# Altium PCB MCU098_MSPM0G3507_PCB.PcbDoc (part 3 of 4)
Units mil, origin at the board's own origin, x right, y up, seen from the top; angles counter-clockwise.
Board outline 2310.03 x 4205.03 mil, 4 copper layers (Top Layer, VCC Layer, GND Layer, Bottom Layer), stack 62.4 mil thick; 260 components, 182 nets, 835 pads, 237 vias.
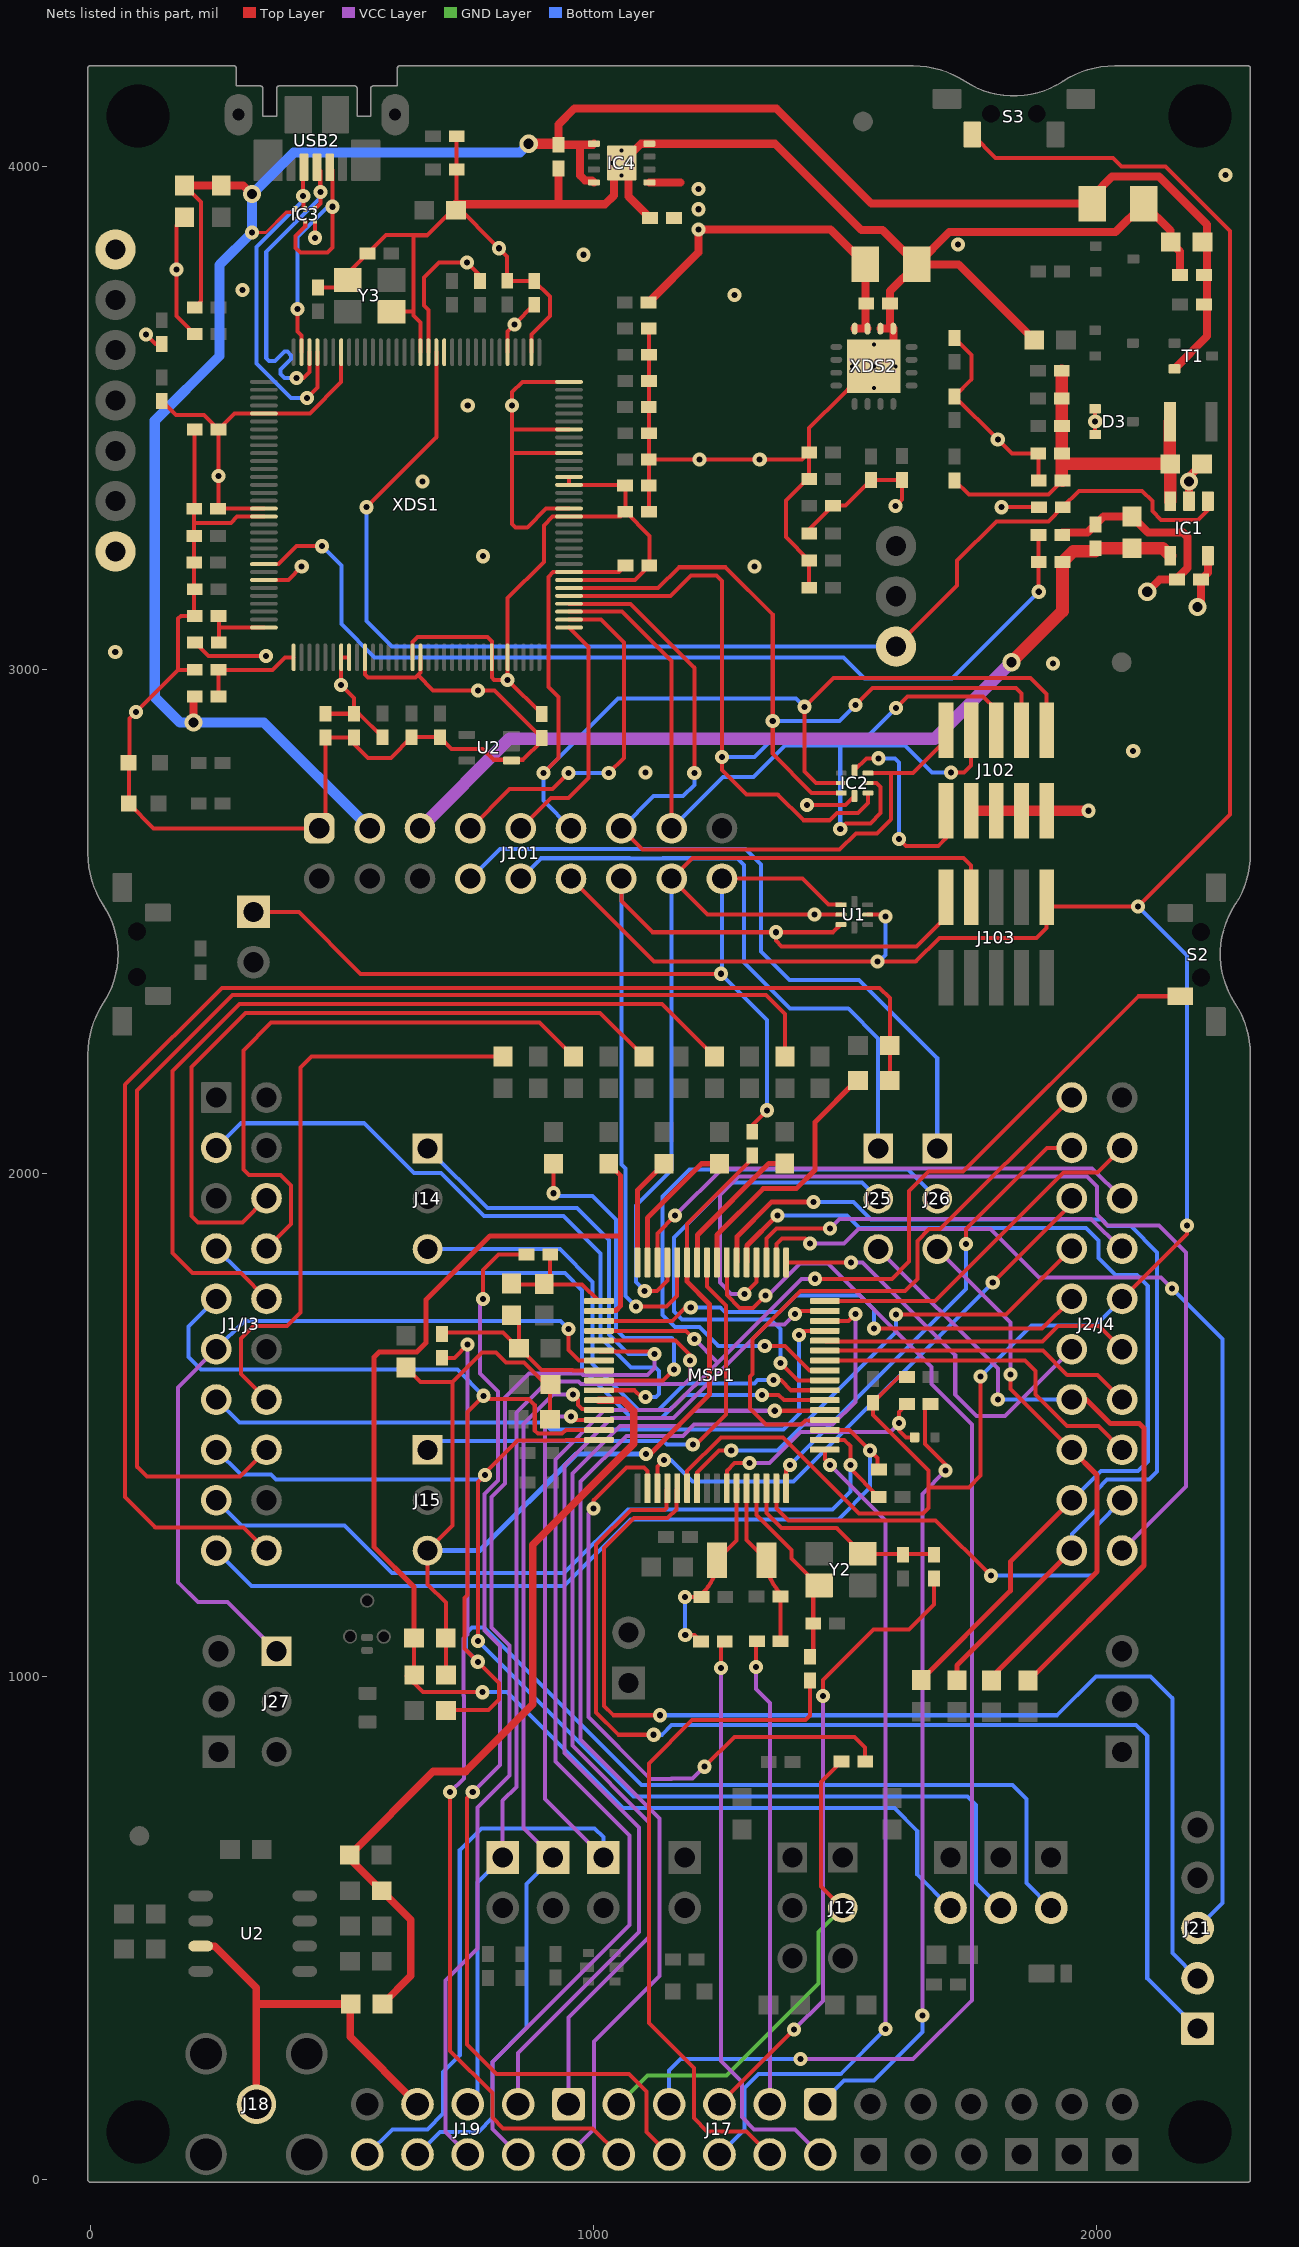
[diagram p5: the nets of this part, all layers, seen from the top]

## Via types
v1: diameter 28, hole 12, Top Layer to Bottom Layer, 211 vias
v2: diameter 36, hole 20, Top Layer to Bottom Layer, 17 vias
v3: diameter 19.68, hole 7.87, Top Layer to Bottom Layer, 9 vias

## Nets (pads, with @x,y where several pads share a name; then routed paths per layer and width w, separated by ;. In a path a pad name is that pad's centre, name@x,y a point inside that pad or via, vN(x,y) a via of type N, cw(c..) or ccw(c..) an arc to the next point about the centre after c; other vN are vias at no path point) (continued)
PA1: MSP1.34 R19.1 | length 1278.6
  Top Layer w8: v1(999.96,1333.33) 999.96,1349.91 1065.04,1414.99 1078.33,1414.99 1078.57,1415.23 1100.26,1415.23 1107.05,1408.44 MSP1.34@1107.05,1373.59 ; v1(1220,820.5) 1279.5,880 1518,880 1539.62,858.38 R19.1@1539.62,830.5
  VCC Layer w8: v1(999.96,1333.33) 990,1323.36 990,919 1112.5,796.5 1154.63,796.5 1154.75,796.62 1196.12,796.62 v1(1220,820.5)
PA1-: J12.2 J17.9 R19.2 | length 991.2
  Top Layer w8: R19.2@1492.38,830.5 1452,790.12 1452,582.88 J12.2@1494.88,540
  GND Layer w8: J17.9@1050,150 1107,207 1264,207 1447,390 1447,492.12 J12.2@1494.88,540
PA2-: J17.1 R9.1 | length 1579
  Top Layer w8: R9.1@1669.62,1541 1658.83,1530.2 1658.83,1461.99 1699.39,1421.43 v1(1699.39,1409)
  VCC Layer w8: v1(1653.02,326.02) 1653.02,1362.63 v1(1699.39,1409)
  Bottom Layer w8: J17.1@1470,170 J17.1@1450,150 1450.8,150 1497.8,197 1557,197 1653.02,293.02 v1(1653.02,326.02)
PA2_ROSC: MSP1.42 R8.1 R9.2 | length 512.1
  Top Layer w8: MSP1.42@1264.53,1373.59 1264.53,1408.53 1280,1424 v1(1310,1424) ; R9.2@1622.38,1541 1607,1525.62 v1(1607,1503) 1607,1489 1621,1475 R8.1@1637.82,1475 R8.1@1638.38,1475
  VCC Layer w8: v1(1310,1424) 1349,1424 1411,1486 1590,1486 v1(1607,1503)
PA3-: J17.2 R10.1 | length 1151.8
  Top Layer w8: v1(1253.03,1017) 1253.03,1060.64 1252.65,1061.02 R10.1@1260.62,1069
  VCC Layer w8: v1(1253.03,1017) 1253.03,236.45 1252.65,236.06 1294.35,194.35 1294.35,124.65 1319,100 1400,100 J17.2@1450,50
PA3_LFXIN: C9.2 MSP1.43 R10.2 Y1.2 | length 390.3
  Top Layer w8: v1(1181.65,1158) C9.2@1214.38,1158 ; v1(1182,1082) 1200.38,1082 R10.2@1213.38,1069 ; C9.2@1208.26,1158.65 ccw(c1155.34,1231) Y1.2@1244.98,1231 1284.21,1270.23 MSP1.43@1284.21,1373.59 MSP1.43@1285.4,1372.4
  Bottom Layer w8: v1(1181.65,1158) 1182,1157.65 v1(1182,1082)
PA4-: J17.3 R11.1 | length 935.8
  Top Layer w8: v1(1322.9,1019) 1322.9,1068.27 R11.1@1324.38,1069.75
  VCC Layer w8: v1(1322.9,1019) 1322.9,974.48 1350,947.38 J17.3@1350,150
  Bottom Layer w8: J17.3@1347,153 J17.3@1350,150
PA4_LFXOUT: C11.2 MSP1.44 R11.2 Y1.1 | length 330.5
  Top Layer w8: MSP1.44@1303.9,1373.59 1303.9,1270.51 Y1.1@1343.4,1231 ccw(c1434.2,1231) C11.2@1378.31,1159.45 ; C11.2@1370.96,1158.65 1370.96,1070.41 R11.2@1371.62,1069.75
PA5-: J17.4 R15.1 | length 1351.7
  Top Layer w8: J17.4@1350,50 1304,96 1225.58,96 1199,122.58 1199,222 1109.62,311.38 1109.62,827.19 1195.43,913 1420.58,913 1430,922.42 R15.1@1430,991.63
PA5_HFXIN: C10.2 MSP1.45 R15.2 Y2.3 | length 394.5
  Top Layer w8: MSP1.45@1323.58,1373.59 1323.58,1320.29 1393,1250.88 1393,1234.33 1446.82,1180.5 Y2.3@1448.05,1180.5 1436.38,1168.83 C10.2@1436.38,1105 1436.38,1045.25 R15.2@1430,1038.87
PA6-: J17.5 R17.1 | length 1262.3
  Top Layer w8: J17.5@1250,150 v1(1398,298) ; v1(1456,961) 1456,993 1556.25,1093.25 1626.75,1093.25 1676.38,1142.88 R17.1@1676.38,1194.38
  VCC Layer w8: v1(1398,298) 1455.35,355.35 1455.35,960.35 v1(1456,961)
PA6_HFXOUT: C12.2 MSP1.46 R17.2 Y2.1 | length 416.4
  Top Layer w8: MSP1.46@1343.27,1373.59 1343.27,1324.73 1372.88,1295.12 1483.04,1295.12 Y2.1@1534.66,1243.5 1674.5,1243.5 R17.2@1676.38,1241.62
PA7_CLK-OUT: J17.6 MSP1.49 | length 1682.5
  Top Layer w8: MSP1.49@1459.41,1450.36 1459.41,1430.59 v1(1470,1420)
  VCC Layer w8: v1(1470,1420) 1580,1310 v1(1580,299)
  Bottom Layer w8: J17.6@1250,50 1300,100 1300,182 1328,210 1491,210 v1(1580,299)
PA8_UART1-TX: J1/J3.4 MSP1.54 | length 1463.6
  Top Layer w8: v1(1334.84,1559.36) 1367.56,1559.36 1378.12,1548.79 MSP1.54@1459.41,1548.79
  Bottom Layer w8: J1/J3.4@250,1850 299,1801 943.19,1801 977.23,1766.97 977.23,1611.32 1075.32,1513.23 1135.02,1513.23 1181.14,1559.36 v1(1334.84,1559.36)
PA9_UART1-RX: J14.3 MSP1.55 | length 1053.4
  Top Layer w8: v1(1357.4,1588.56) 1372.09,1588.56 1392.17,1568.47 MSP1.55@1459.41,1568.47 MSP1.55@1457.5,1566.57
  Bottom Layer w8: J14.3@670,1849 933,1849 998,1784 998,1620.43 1089.33,1529.1 1128.44,1529.1 1181.34,1582 1319.47,1582 1326.03,1588.56 v1(1357.4,1588.56)
PA10_UART0-TX: J25.2 MSP1.56 | length 1006
  Top Layer w8: v1(1371.1,1623) 1405.94,1588.16 MSP1.56@1459.41,1588.16
  Bottom Layer w8: v1(1371.1,1623) 1371.1,1689.75 1351.84,1709 1175.85,1709 1160,1724.85 1160,1871.97 1269.03,1981 1533.39,1981 J25.2@1565.39,1949
PA10_UART0-TX_BP: J2/J4.34 J25.3 R62.2 | length 1299.4
  Top Layer w10: R62.2@1870.5,997.5 2093.39,1220.39 2093.39,1493.28 2084.66,1502 2026.83,1502 1978.83,1550 J2/J4.34@1950,1550
  VCC Layer w8: J25.3@1565.39,1849 1803,1611.39 v1(1803,1550)
  Bottom Layer w8: v1(1803,1550) J2/J4.34@1950,1550
PA10_UART0-TX_XDS: J25.1 J101.10 | length 1208.3
  Bottom Layer w8: J101.10@855.36,2585 J101.10@855,2585 895.51,2625.51 1071.78,2625.51 1072.21,2625.08 1137.79,2625.08 1138.22,2625.51 1285.49,2625.51 1299,2612 1299,2418 1390,2327 1505.91,2327 1565.39,2267.52 J25.1@1565.39,2049
PA11_UART0-RX: J26.2 MSP1.57 | length 1195.9
  Top Layer w8: v1(1340,1656.33) 1380.58,1656.33 1429.06,1607.84 MSP1.57@1459.41,1607.84 MSP1.57@1460.44,1608.87
  Bottom Layer w8: v1(1340,1656.33) 1247.61,1656.33 1209.94,1694 1161.41,1694 1137.28,1718.13 1137.28,1953.27 1190.69,2006.68 1625.04,2006.68 J26.2@1682.72,1949
PA11_UART0-RX_BP: J2/J4.33 J26.3 R63.2 | length 1075.7
  Top Layer w8: v1(1828.25,1599.89) 1828.25,1571.09 1949.34,1450 J2/J4.33@1950,1450
  Top Layer w10: R63.2@1790.84,991.75 1790.84,998.84 2000,1208 2000,1400 J2/J4.33@1950,1450
  VCC Layer w8: J26.3@1682.72,1849 1828.25,1703.47 v1(1828.25,1599.89)
PA11_UART0-RX_XDS: J26.1 J101.8 | length 1404.2
  Bottom Layer w8: J101.8@755,2585 813.84,2643.84 1301.67,2643.84 1332.87,2612.64 1332.87,2440.6 1389.62,2383.85 1527.08,2383.85 1682.72,2228.2 J26.1@1682.72,2049
PA12_CAN-TX: J2/J4.32 MSP1.5 R64.2 | length 1946.6
  Top Layer w10: MSP1.5@1303.9,1822.41 1304.8,1823.32 1304.8,1856.16 1364.64,1916 v1(1365,1916) ; R64.2@1650.84,992.75 1828,1169.91 1828,1228 J2/J4.32@1950,1350
  Bottom Layer w8: v1(1365,1916) 1503.25,1916 1528.4,1890.86 1978.74,1890.86 2003.52,1866.07 2003.52,1831.21 2036.9,1797.83 2079.21,1797.83 2101,1776.03 2101,1427 2081.63,1407.63 2007.63,1407.63 J2/J4.32@1950,1350
PA13_CAN-RX: J2/J4.31 MSP1.6 R65.2 | length 2020.6
  Top Layer w10: MSP1.6@1284.21,1822.41 1285.12,1823.31 1285.12,1874.12 1353.87,1942.87 1436.38,1942.87 v1(1437.13,1942.13) ; R65.2@1721.84,992.25 1721.84,1021.84 J2/J4.31@1950,1250
  Bottom Layer w8: v1(1437.13,1942.13) 1516.36,1942.13 1551.04,1907.44 2009.76,1907.44 2022.36,1894.84 2067.38,1894.84 2119.69,1842.53 2119.69,1407 2103.69,1391 2020.36,1391 2000,1370.64 2000,1332.89 1950,1282.89 J2/J4.31@1950,1250
PA14_TIMH0-C0: J17.7 MSP1.7 | length 2626.2
  Top Layer w8: MSP1.7@1264.53,1822.41 1264.53,1757.47 1290,1732 1316.83,1732 v1(1341.69,1756.86) v1@1341.69,1751.92
  VCC Layer w8: v1(1341.69,1756.86) 1346.64,1756.86 1409.78,1820 1465.67,1820 1671,1614.67 1671,1581 1751.48,1500.52 1751.48,356.48 1635,240 v1(1410.76,240)
  Bottom Layer w8: J17.7@1150,150 1150,217 1173,240 v1(1410.76,240)
PA15-_DAC-OUT: C45.1 J1/J3.30 R55.2 | length 2915.9
  Top Layer w8: J1/J3.30@350,1250 304,1296 129,1296 69,1356 69,2175.5 261.31,2367.81 1568.19,2367.81 1588.53,2347.47 C45.1@1588.53,2253.53 1588.53,2184.09 R55.2@1588.19,2183.75
PA15_DAC-OUT: MSP1.8 R55.1 | length 517.5
  Top Layer w10: MSP1.8@1244.84,1822.41 1244.84,1876.84 1337,1969 1402.68,1969 1439.73,2006.05 1439.73,2101 1522.48,2183.75 R55.1@1525.19,2183.75
PA16_OPA1-OUT_ADC1.1: J15.1 MSP1.9 | length 947.7
  Top Layer w8: v1(1197,1460.41) 1203.17,1460.41 1262.72,1519.96 1262.72,1736.83 1225.16,1774.39 MSP1.9@1225.16,1822.41
  Bottom Layer w8: J15.1@670,1450 690,1470 692.13,1467.87 1138.22,1467.87 1145.68,1460.41 v1(1197,1460.41)
PA17-_ADC1.2: J1/J3.28 R81.1 | length 2500.1
  Top Layer w8: J1/J3.28@350,1450 297.21,1397.21 112.29,1397.21 93,1416.5 93,2164 282.82,2353.81 1342.19,2353.81 1380,2316 R81.1@1380,2231.5
PA17_OPA1-IN-_ADC1.2: MSP1.10 R82.2 | length 287.4
  Top Layer w10: MSP1.10@1205.47,1822.41 1206.38,1823.32 1206.38,1877.02 1348.62,2019.25 R82.2@1379.84,2019.25
PA18-: J8.1 J101.18 R23.1 U1.5 | length 1791.5
  Top Layer w8: J8.1@324.12,2518.97 414.28,2518.97 537.25,2396 v1(1253.01,2396) ; J101.18@1255,2585 1414.56,2585 1466.39,2533.17 U1.5@1491.35,2533.17 ; R23.1@1315.24,2082.16 1315.24,2095.31 v1(1344.68,2124.75)
  Bottom Layer w8: J101.18@1255,2585 1255,2397.99 v1(1253.01,2396) 1344.68,2304.33 v1(1344.68,2124.75)
PA18_OPA1-IN+_ADC1.3_GPAMP-IN-: C46.1 J15.3 MSP1.11 R23.2 R58.2 R61.1 R66.2 R67.2 | length 2273.1
  Top Layer w8: R58.2@627,1613.81 656.12,1584.69 720,1584.69 ; R61.1@706.48,1003.04 C46.1@706.48,1076.28 ; C46.1@706.48,1076.72 706.48,1146.52 670,1183 J15.3@670,1250 720,1300 720,1520.81 720,1584.69 ; R66.2@914.5,1512 R66.2@913.5,1511 913.5,1579 R67.2@914.5,1580 905.16,1580 861.86,1623.3 825.91,1623.3 806.18,1643.03 778.34,1643.03 720,1584.69 ; MSP1.11@1185.79,1822.41 1185.79,1899.11 1315.24,2028.56 R23.2@1315.24,2034.92
  Top Layer w10: v1(1104,1442) 1112.31,1442 1230,1559.69 1230,1740 1185.79,1784.21 MSP1.11@1185.79,1822.41
  Bottom Layer w10: J15.3@670,1250 774,1250 966,1442 v1(1104,1442)
PA19_SWDIO: J101.14 J103.2 MSP1.12 U1.7 | length 1955
  Top Layer w8: J101.14@1055,2585 1055,2540.68 1117.18,2478.5 v1(1362,2478.5) ; v1(1084,1734.69) 1144.69,1734.69 1166.1,1756.1 MSP1.12@1166.1,1822.41 ; U1.7@1491.35,2493.8 1476.05,2478.5 v1(1362,2478.5) ; J103.2@1700,2548.12 1700,2509 1641.5,2450.5 1373.5,2450.5 1362,2462 v1(1362,2478.5)
  Bottom Layer w8: J101.14@1055,2585 1055,2017.39 1063.1,2009.29 1063.1,1755.59 v1(1084,1734.69)
PA20_SWCLK: J101.16 J103.4 MSP1.13 U1.6 | length 1993
  Top Layer w8: v1(1101.5,1765.53) 1125.53,1765.53 1146.42,1786.42 MSP1.13@1146.42,1822.41 ; U1.6@1491.35,2513.49 v1(1439,2513.49) 1226.51,2513.49 J101.16@1155,2585 1196,2626 1735.29,2626 1750,2611.29 J103.4@1750,2548.12
  Bottom Layer w8: v1(1101.5,1765.53) 1083.89,1783.15 1083.89,1935.14 1155,2006.25 J101.16@1155,2585
PA21-: J17.8 R20.1 | length 2245.6
  Top Layer w8: v1(759.86,770) 748,758.14 748,269 807.34,209.66 1070.65,209.66 1105,175.31 1105,95 J17.8@1150,50 ; v1(780,1750.03) 780,1806.97 811.03,1838 R20.1@866.42,1838
  VCC Layer w8: v1(759.86,770) 814,824.14 814,1060.15 783,1091.15 783,1362.41 809.87,1389.28 809.87,1565.72 774.05,1601.54 774.05,1744.08 v1(780,1750.03)
PA21_VREF-: C8.2 MSP1.17 R3.2 R20.2 | length 232.6
  Top Layer w8: C8.2@836.63,1780.5 838.13,1779 977.23,1779 MSP1.17@1010.59,1745.64 ; R3.2@913.66,1793.84 R20.2@913.66,1838
PA22-_ADC0.7: J1/J3.24 R83.1 | length 1197.4
  Top Layer w8: J1/J3.24@350,1850 398.91,1898.91 398.91,1975.01 377.92,1996 315,1996 304,2007 304,2244 359.24,2299.24 892.25,2299.24 R83.1@960,2231.5
PA22_OPA0-OUT_ADC0.7_GPAMP-OUT_COMP2-IN0+: C46.2 J1.2 MSP1.18 R61.2 R84.2 | length 2965
  Top Layer w8: R61.2@628.5,1001.04 661.05,968.5 v1(779,968.5) ; R61.2@643.27,1003.26 C46.2@643.27,1076.5
  Top Layer w10: C46.2@643.27,1076.5 643.27,1177.44 564,1256.7 564,1634.5 574,1644.5 648.64,1644.5 667,1662.86 667,1748.34 793.66,1875.01 1051.99,1875.01 1052.99,1874 ; MSP1.18@1010.59,1725.95 1010.59,1726.86 1044.31,1726.86 1052.99,1735.54 1052.99,1874 ; R84.2@1030,2018.5 1052.99,1995.51 1052.99,1874
  Bottom Layer w8: v1(779,968.5) 828.2,968.5 1058.7,738 1598,738 1643,693 1643,606 J1.2@1709,540
PA23-: J17.10 R22.1 | length 1928.3
  Top Layer w8: R22.1@699,1633.01 723.31,1633.01 v1(749.42,1659.12) ; v1(715,770) 715,256 799,172 799,123.09 820.25,101.84 998.16,101.84 J17.10@1050,50
  VCC Layer w8: v1(715,770) 742.44,797.44 742.44,961.19 741.57,962.06 741.57,1075.31 749.42,1083.15 v1(749.42,1659.12)
PA23_VREF+: C7.1 C8.1 MSP1.24 R22.2 | length 429.5
  Top Layer w8: R22.2@699,1679.62 R22.2@699.32,1679.94 ; R22.2@699,1680.25 701.87,1683.12 820.38,1683.12 C7.1@851.5,1652 ; C8.1@836.63,1717.5 851.5,1702.63 C7.1@851.5,1652 ; C8.1@842,1719.38 C8.1@851.5,1709.87 ; MSP1.24@1010.59,1607.84 958.65,1607.84 957.8,1608.7 896.25,1608.7 852.95,1652 C7.1@851.5,1652
PA24-_ADC0.3: J1/J3.27 R79.1 | length 1179.9
  Top Layer w8: J1/J3.27@350,1550 299.61,1600.39 299.61,1671.35 324.26,1696 391,1696 417.5,1722.5 417.5,2209.5 439.5,2231.5 R79.1@820,2231.5
PA24_OPA0-IN1-_ADC0.3: MSP1.25 R80.2 | length 763.8
  Top Layer w8: v1(920,1959.93) R80.2@920,2018.5 ; MSP1.25@1010.59,1588.16 1070.78,1588.16 1092.24,1588.13 ; 1092.28,1588.16 1138.16,1588.16 v1(1160,1610)
  Bottom Layer w8: v1(920,1959.93) 925.93,1954 998,1954 1044.2,1907.8 1044.2,1720.8 1044.13,1720.72 1044.13,1689.28 1061.11,1672.29 1155.21,1672.29 1160,1667.5 v1(1160,1610)
PA25_OPA0-IN1+_ADC0.2: J1/J3.2 MSP1.26 | length 1375.6
  Top Layer w8: MSP1.26@1010.59,1568.47 1081.53,1568.47 1095,1555 v1(1102.68,1555)
  Bottom Layer w8: J1/J3.2@250,2050 299,2099 543.75,2099 642.75,2000 696.55,2000 782.29,1914.26 940.37,1914.26 1014.07,1840.56 1014.07,1673.25 1063.04,1624.28 1063.57,1624.28 1074.13,1613.72 1123.28,1613.72 1130,1607 1130,1561 1124,1555 v1(1102.68,1555)
PA26_OPA0-IN0+_GPAMP-IN+_COMP0-IN0+: J1/J3.5 J3.2 MSP1.30 R57.1 | length 3414.5
  Top Layer w8: R57.1@692.16,937.39 692.16,933 791,933 812,954 812,986.82 743.05,1055.78 743.05,1156.13 749,1162.08 749,1525 v1(781.5,1557.5) 787.7,1551.3 870.6,1551.3 883,1538.9 883,1488.97 889.67,1482.3 937.32,1482.3 944.76,1489.73 MSP1.30@1010.59,1489.73
  Bottom Layer w8: J1/J3.5@227.51,1750 J1/J3.5@250,1750 195.25,1695.25 195.25,1634.16 219.92,1609.49 729.51,1609.49 v1(781.5,1557.5) ; v1(769.82,1029) 746.21,1052.61 746.21,1084.88 758.33,1097 782.5,1097 1095.5,784 1832,784 1860,756 1860,589 J3.2@1909,540
PA27_OPA0-IN0-_COMP0-IN0-_TIMA2_FAL: J1/J3.8 J2.2 MSP1.31 | length 2505.3
  Top Layer w8: v1(770.21,1070) 770.21,1386.21 v1(784,1400) 784,1403.97 848.33,1468.3 943.12,1468.3 944.87,1470.05 MSP1.31@1010.59,1470.05
  Bottom Layer w8: J1/J3.8@250,1450 299.03,1400.97 358.97,1400.97 368.94,1391 652.45,1391 652.85,1391.4 687.15,1391.4 687.55,1391 775,1391 v1(784,1400) ; v1(770.21,1070) 1079.21,761 1743,761 1760,744 1760,589 J2.2@1809,540
PA28_TIMA2_C0: J2/J4.38 MSP1.35 | length 1128.9
  Top Layer w8: MSP1.35@1126.73,1373.59 1126.73,1416.73 v1(1140,1430) ; v1(1793.04,1782.83) 1950,1939.79 J2/J4.38@1950,1950
  Bottom Layer w8: v1(1140,1430) 1153.62,1430 1196.59,1387.03 1397.24,1387.03 v1(1793.04,1782.83)
PA29_TIMG10_C0: J21.1 MSP1.36 | length 2295.9
  Top Layer w8: v1(1119.38,884) 1049.27,884 1005.13,928.15 1005.13,1261.58 1073.99,1330.44 1140.45,1330.44 1144.51,1334.5 1144.51,1371.69 MSP1.36@1146.42,1373.59
  Bottom Layer w8: v1(1119.38,884) 1136,884 1155,903 1160.62,903 2078,903 2086.65,894.35 2087.4,894.35 2100,881.75 2100,400 J21.1@2200,300
PA30_TIMG10_C1: J21.2 MSP1.37 | length 2295.1
  Top Layer w8: v1(1132,922.75) 1039.73,922.75 1021,941.48 1021,1255 1080.56,1314.56 1147.02,1314.56 1164.2,1331.74 1164.2,1371.68 MSP1.37@1166.1,1373.59
  Bottom Layer w8: v1(1132,922.75) 1920.82,922.75 1998.07,1000 2106.5,1000 2150,956.5 2150,450 J21.2@2200,400
PA31_TIMA2_C1: J2/J4.37 MSP1.39 | length 980.5
  Top Layer w8: MSP1.39@1205.47,1373.59 1205.47,1404.99 1249.48,1449 v1(1273.42,1449) ; v1(1600.5,1719.11) 1819.11,1719.11 J2/J4.37@1950,1850
  Bottom Layer w8: v1(1273.42,1449) 1365,1449 1600.5,1684.5 v1(1600.5,1719.11)
PB0_SPI1-CS2: J2/J4.12 MSP1.47 | length 898.3
  Top Layer w8: MSP1.47@1362.95,1373.59 1362.95,1333.77 1386.72,1310 1679.72,1310 v1(1789.72,1200)
  Bottom Layer w8: v1(1789.72,1200) 1992,1200 2000,1208 2000,1300 J2/J4.12@2050,1350
PB1_TIMA1-C1: J2/J4.39 MSP1.48 | length 941.3
  Top Layer w8: MSP1.48@1382.64,1373.59 1382.64,1412.55 v1(1390,1419.92) ; v1(1739.48,1859) 1739.48,1888.79 1900.69,2050 J2/J4.39@1950,2050
  Bottom Layer w8: v1(1390,1419.92) 1739.48,1769.4 v1(1739.48,1859) v1@1739.48,1860
PB2_I2C1-SCL: J1/J3.9 MSP1.50 R59.2 | length 1620.2
  Top Layer w8: MSP1.50@1459.41,1470.05 1497.95,1470.05 1510,1458 v1(1510,1419.92) 1510,1412.72 R59.2@1566.38,1356.35
  Bottom Layer w8: J1/J3.9@250,1350 300,1300 504.84,1300 599.84,1205 941.52,1205 1068.52,1332 1474.28,1332 1510,1367.72 v1(1510,1419.92)
PB3_I2C1-SDA: J1/J3.10 MSP1.51 R60.2 | length 1630.6
  Top Layer w8: MSP1.51@1459.41,1489.73 1508.62,1489.73 v1(1549.35,1449) 1564.09,1434.26 R60.2@1564.09,1414.34
  Bottom Layer w8: J1/J3.10@250,1250 320.13,1179.87 940.96,1179.87 1073.18,1312.09 1486.09,1312.09 1549.35,1375.35 v1(1549.35,1449)
PB4_TIMA1-C0: J2/J4.40 MSP1.52 | length 1183
  Top Layer w8: MSP1.52@1459.41,1509.42 1458.62,1508.63 1421,1508.63 1412.37,1500 1342.85,1500 1310.84,1532.02 1310.84,1595.49 1316,1600.65 1316,1669.98 1411.29,1765.28 1618.78,1765.28 1643.19,1789.69 1643.19,1865.37 1666.35,1888.53 1688.53,1888.53 J2/J4.40@1950,2150
PB5: J19.1 MSP1.53 | length 1936
  Top Layer w8: v1(1359.9,1527.77) 1458.08,1527.77 MSP1.53@1459.41,1529.1
  VCC Layer w8: J19.1@950,150 950,322 1109.96,481.96 1109.96,710.04 957.76,862.24 957.76,1402.76 1052.35,1497.35 1167.65,1497.35 1198.08,1527.77 v1(1359.9,1527.77)
PB6_SPI1-CS0: J2/J4.13 MSP1.58 | length 691.7
  Top Layer w8: MSP1.58@1459.41,1627.53 1857.47,1627.53 1878,1607 1878,1560 1941,1497 2003,1497 J2/J4.13@2050,1450
PB7_SPI1-POCI: J2/J4.14 MSP1.59 | length 630.9
  Top Layer w8: MSP1.59@1459.41,1647.21 1892.81,1647.21 1941.02,1599 2001,1599 J2/J4.14@2050,1550
PB8_SPI1-PICO: J2/J4.15 MSP1.60 | length 623.2
  Top Layer w8: MSP1.60@1459.41,1666.9 1461.18,1665.13 1891.63,1665.13 1922.5,1696 2004,1696 J2/J4.15@2050,1650
PB9_SPI1-SCK: J1/J3.7 MSP1.61 | length 1408.9
  Top Layer w8: v1(1408,1678) 1416.58,1686.58 MSP1.61@1459.41,1686.58
  Bottom Layer w8: J1/J3.7@250,1550 296,1504 900.43,1504 913.95,1490.48 1377.48,1490.48 1410,1523 1408,1525 v1(1408,1678)
PB10_TIMG0-C0: J19.2 MSP1.62 | length 2329.7
  Top Layer w8: MSP1.62@1459.41,1706.27 1506.27,1706.27 v1(1520,1720)
  VCC Layer w8: J19.2@950,50 1000.49,100.49 1000.49,274.49 1130.54,404.54 1130.54,717.99 973.63,874.91 973.63,1386.77 1064.86,1478 1177.16,1478 1199.16,1500 1474.9,1500 1520,1545.1 v1(1520,1720)
PB11_TIMG0-C1: J19.3 MSP1.63 | length 2074.6
  Top Layer w8: v1(1399.96,1720) 1405.91,1725.95 MSP1.63@1459.41,1725.95
  VCC Layer w8: J19.3@850,150 850,252.03 1090,492.03 1090,699.52 941.88,847.63 941.88,1419.3 1035.8,1513.22 1158.63,1513.22 1344.44,1699.04 1378.99,1699.04 v1(1399.96,1720)
PB12_TIMA0-C2_TIMA1-FAL: J2/J4.19 MSP1.64 | length 716.7
  Top Layer w8: MSP1.64@1459.41,1745.64 1678.64,1745.64 1934,2001 2001,2001 J2/J4.19@2050,2050
PB13_TIMA0-C3: J2/J4.35 MSP1.1 | length 794.1
  Top Layer w8: MSP1.1@1382.64,1822.41 v1(1511.63,1822.41)
  VCC Layer w8: v1(1511.63,1822.41) 1534.42,1822.41 1718.49,1638.34 1718.49,1560.23 1760.98,1517.74 1817.74,1517.74 J2/J4.35@1950,1650
PB14_TIMG10_IDX: J21.3 MSP1.2 | length 2225.1
  Top Layer w8: MSP1.2@1362.95,1822.41 1362.95,1858.9 1373.92,1869.87 1420.25,1869.87 v1(1430,1860.12)
  VCC Layer w8: v1(1430,1860.12) 1497.66,1860.12 1526.07,1888.53 1788.77,1888.53 1884.91,1792.39 2127.7,1792.39 v1(2149.08,1771)
  Bottom Layer w8: v1(2149.08,1771) 2249.92,1670.16 2249.92,549.92 J21.3@2200,500
PB15_UART2-TX_TIMG1-C0: J2/J4.17 MSP1.3 | length 794.8
  Top Layer w8: MSP1.3@1343.27,1822.41 1343.27,1869.87 1363.52,1890.13 v1(1469.76,1890.13)
  VCC Layer w8: v1(1469.76,1890.13) 1488.63,1909 1988.4,1909 2047.4,1850 J2/J4.17@2050,1850
PB16_UART2-RX_TIMG1-C1: J2/J4.11 MSP1.4 | length 1986
  Top Layer w8: v1(1300,1759.93) 1323.58,1783.51 MSP1.4@1323.58,1822.41
  VCC Layer w8: v1(1300,1759.93) 1273.42,1759.93 1251.22,1782.14 1251.22,1956.22 1288.32,1993.32 1980.09,1993.32 1999.82,1973.59 1999.82,1917.38 2021.03,1896.18 2123.34,1896.18 2177,1842.52 2177,1377 J2/J4.11@2050,1250
PB17_ADC1.4_SPI1-CS1: J2/J4.18 MSP1.14 | length 1059.3
  Top Layer w8: MSP1.14@1126.73,1822.41 1126.73,1880.31 v1(1162,1915.58)
  VCC Layer w8: v1(1162,1915.58) 1255.89,2009.47 1990.53,2009.47 J2/J4.18@2050,1950
PB18-_ADC1.5: J1/J3.25 R75.1 | length 1761.9
  Top Layer w8: J1/J3.25@350,1750 299,1801 203.27,1801 163,1841.27 163,2203 296,2336 1135.5,2336 R75.1@1240,2231.5
PB18_ADC1.5: MSP1.15 R76.2 | length 276.1
  Top Layer w10: MSP1.15@1107.05,1822.41 1107.05,1911.05 1214.5,2018.5 R76.2@1250,2018.5
PB19-_ADC1.6: J1/J3.23 R77.1 | length 1449.8
  Top Layer w8: J1/J3.23@350,1950 302,1902 214,1902 201,1915 201,2211 308.45,2318.45 1013.05,2318.45 R77.1@1100,2231.5
PB19_OPA1-IN+_ADC1.6: MSP1.16 R78.2 | length 217.9
  Top Layer w10: MSP1.16@1087.36,1822.41 1087.36,1965.87 R78.2@1140,2018.5
PB20_TIMA0-C2: J2/J4.36 MSP1.19 | length 1041.6
  Top Layer w8: MSP1.19@1010.59,1706.27 1156.2,1706.27 1182.93,1733 v1(1193,1733) ; v1(1557,1691) 1891,1691 J2/J4.36@1950,1750
  Bottom Layer w8: v1(1193,1733) 1251.58,1733 1260.71,1723.87 1369.18,1723.87 1401.84,1756.54 1529.46,1756.54 1557,1729 v1(1557,1691)
PB21: J19.4 MSP1.20 S2.3 | length 3542.8
  Top Layer w8: MSP1.20@1010.59,1686.58 1183.42,1686.58 v1(1200,1670) ; v1(1440,1790) 1592.89,1790 1626.9,1824.02 1626.9,1964.22 1665.53,2002.84 1734.16,2002.84 2082.65,2351.32 S2.3@2165.44,2351.32
  VCC Layer w8: J19.4@850,50 799,101 799,234 1071,506 1071,684 923.97,831.03 923.97,1430.97 1022.09,1529.09 1152.05,1529.09 1246.98,1624.02 ; v1(1200,1670) 1245.98,1624.02 1246.98,1624.02 ; v1(1440,1790) 1412.96,1790 1246.98,1624.02
PB22: J5.1 J19.5 MSP1.21 | length 2029.8
  Top Layer w8: MSP1.21@1010.59,1666.9 1162.52,1666.9 1191.28,1638.14 v1(1191.28,1628)
  VCC Layer w8: J5.1@819.38,640 819.38,752.88 847.03,780.53 847.03,1524.5 908.4,1585.87 969.72,1585.87 974.69,1580.91 1180.24,1580.91 1191.28,1591.94 v1(1191.28,1628)
  Bottom Layer w8: J19.5@750,150 769.66,169.66 769.66,590.28 J5.1@819.38,640
PB23_TIMA0-FAL: J14.1 J19.6 MSP1.22 | length 2794.6
  Top Layer w8: MSP1.22@1010.59,1647.21 1012.5,1645.31 1115.43,1645.31 v1(1120.58,1640.16)
  VCC Layer w8: J19.6@750,50 705.65,94.35 705.65,168.73 706,169.08 706,395.79 769.38,459.17 769.38,739.47 833.03,803.12 833.03,1060.92 797,1096.95 797,1356.61 823.87,1383.48 823.87,1553.66 871.97,1601.75 976.29,1601.75 979.04,1599 1107.22,1599 1120.58,1612.37 v1(1120.58,1640.16)
  Bottom Layer w8: J14.1@670,2049 788.87,1930.13 966.96,1930.13 1030.2,1866.89 1030.2,1726.59 1030.13,1726.52 1030.13,1679.64 1069.61,1640.16 v1(1120.58,1640.16)
PB24_ADC0.5_COMP1-IN1+: J1/J3.6 J27.1 MSP1.23 | length 1587.9
  Top Layer w8: v1(950,1690) 950,1648.83 971.3,1627.53 MSP1.23@1010.59,1627.53
  VCC Layer w8: J1/J3.6@250,1650 174,1574 174,1187 213.5,1147.5 272.5,1147.5 J27.1@370,1050
  Bottom Layer w8: J1/J3.6@250,1650 306.27,1706.27 933.73,1706.27 v1(950,1690)
PB25-: J18.1 J19.7 R74.1 U2.3@219.32,463.99 | length 819.1
  Top Layer w15: U2.3@219.32,463.99 247.01,463.99 330,381 330,352 ; J18.1@330,150 330,352 ; R74.1@517.5,349 R74.1@516.41,349 ; J19.7@650,150 516.41,283.59 R74.1@516.41,349 ; 330,352 333,349 R74.1@516.41,349
PB25_ADC0.4_TIMA2-FAL: C47.1 MSP1.27 R72.2 R74.2 | length 1601.5
  Top Layer w15: R74.2@580.5,349 637.01,405.51 637.01,515.98 R72.2@579,573.99 515.51,637.48 C47.1@515.51,644.99 681.52,811 745.48,811 879.45,944.97 879.45,1261.22 1080,1461.76 1080,1527 1058.21,1548.79 MSP1.27@1010.59,1548.79
PB26: J6.1 J19.8 MSP1.28 | length 1826.1
  Top Layer w8: v1(959,1560) 969.19,1549.81 969.19,1539.11 977.29,1531.01 991.09,1531.01 991.09,1529.1 MSP1.28@1010.59,1529.1
  VCC Layer w8: J6.1@919.38,640 861.03,698.35 861.03,1501.88 919.34,1560.19 919.53,1560 v1(959,1560)
  Bottom Layer w8: J19.8@650,50 694.98,94.98 770.89,94.98 799,123.09 799,234 867,302 867,587.62 J6.1@919.38,640
PB27: J7.1 J19.10 MSP1.29 | length 2105.7
  Top Layer w8: v1(955.35,1516.35) 955.35,1514.2 960.13,1509.42 MSP1.29@1010.59,1509.42
  VCC Layer w8: v1(955.35,1516.35) 909.14,1516.35 902.91,1510.12 902.91,756.47 J7.1@1019.38,640
  Bottom Layer w8: J19.10@550,50 600.13,100.13 670,100.13 701,131.13 701,214.21 734,247.21 734,654.62 777.38,698 1002,698 1019.38,680.62 J7.1@1019.38,640
R\S\T\: C6.1 J2/J4.16 J101.12 J103.10 MSP1.38 R2.1 S3.4 U1.2 | length 5908.3
  Top Layer w8: J101.12@955,2585 1120.08,2419.92 1242.99,2419.92 1243.07,2420 v1(1564.09,2420) 1640,2420 1687,2467 1880,2467 1900,2487 J103.10@1900,2530 ; MSP1.38@1185.79,1373.59 1185.79,1407.75 1253.03,1475 1376.69,1475 1527.69,1324 1654.64,1324 1665.49,1334.85 1665.49,1375.35 ; U1.2@1544.5,2513.49 1576.39,2513.49 v1(1579.88,2510) ; C6.1@1622.38,1595 1606.24,1595 R2.1@1555,1543.76 1555,1519.62 1665.49,1409.13 1665.49,1375.35 ; S3.4@1752.32,4063.44 1798.76,4017 2031.55,4017 2048.68,3999.87 2136.13,3999.87 2264.13,3871.87 2264.13,2712.63 v1(2081.5,2530) J103.10@1900,2530 ; v1(1769,1596) 1769,1398.68 1745.67,1375.35 1665.49,1375.35 ; J103.10@1900,2548.12 J103.10@1900,2530 ; J2/J4.16@2050,1750 2179.06,1879.06 v1(2179.06,1895.44)
  Bottom Layer w8: v1(1564.09,2420) 1566.38,2420 1579.88,2433.5 v1(1579.88,2510) ; v1(1769,1596) 1870,1697 1997,1697 J2/J4.16@2050,1750 ; v1(2081.5,2530) 2179.06,2432.44 v1(2179.06,1895.44)
REF_MAIN_LDO: R51.1 R54.2 XDS1.128 | length 143.9
  Top Layer w8: R54.2@254.62,3107 255.24,3106.38 255.24,3086.5 ; R51.1@255.24,3054 255.24,3086.5 ; XDS1.128@344.85,3083.91 257.84,3083.91 255.24,3086.5
REF_TARGET_VCC: R50.1 R53.2 XDS1.120 | length 1915.4
  Top Layer w8: XDS1.120@344.85,3209.89 373.97,3209.89 409.58,3245.5 v1(460,3245.5) ; R53.2@1884,3268 1884,3214.38 R50.1@1884.38,3214 v1(1884.38,3155)
  Bottom Layer w8: v1(460,3245.5) 498.64,3206.86 498.64,3090.77 564.56,3024.85 1496.15,3024.85 1538,2983 1712.38,2983 v1(1884.38,3155)
VBUS_DETECT: R87.2 R88.2 XDS1.1 | length 212.5
  Top Layer w8: R87.2@254.62,2947 R88.2@254.62,3000 361.65,3000 386.5,3024.85 XDS1.1@403.84,3024.85
VCCEN1: IC1.1 R49.2 TP2.1 XDS1.78 | length 2503.4
  Top Layer w8: v1(548.34,3323) 687.37,3462.03 XDS1.78@687.37,3631.15 ; TP2.1@1601,3046 1722,3167 1722,3217 1800,3295 1904,3295 R49.2@1932,3323 1964,3355 2090,3355 2110,3335 2110,3315 2127,3298 2201,3298 2220.4,3317.4 IC1.1@2220.4,3335
  Bottom Layer w8: v1(548.34,3323) 548.34,3096.66 599,3046 TP2.1@1601,3046
VCCEN2: XDS1.77
XDS_DM: IC3.5 USB2.2 XDS1.93 | length 683.3
  Top Layer w8: USB2.2@424.5,3998.28 423,3996.78 v1(423,3941) 423.13,3940.87 423.13,3919.69 IC3.5@427,3915.81 ; v1(430.17,3540.08) 451.15,3561.06 XDS1.93@451.15,3631.15
  Bottom Layer w8: v1(423,3941) 423,3932.88 330.47,3840.34 330.47,3608.66 399.05,3540.08 v1(430.17,3540.08)
XDS_DP: IC3.4 USB2.3 XDS1.94 | length 684.8
  Top Layer w8: v1(410.02,3580) 423.55,3580 435.4,3591.85 XDS1.94@435.4,3631.15 ; IC3.4@446.69,3915.81 457,3926.13 v1(457,3949.4) 456.82,3949.58 456.82,3990.98 455.56,3992.24 449.81,3997.99 USB2.3@450.09,3998.28 USB2.3@454.95,3993.42
  Bottom Layer w8: v1(410.02,3580) 385.64,3580 377.64,3588 377.64,3596.37 399.05,3617.77 399.05,3624.75 391.28,3632.52 385.37,3632.52 366.66,3613.81 355.38,3613.81 349.51,3619.68 349.51,3830.51 457,3938 v1(457,3949.4)
XDS_GND: C13.2 C14.2 C15.2 C16.2 C17.2 C18.2 C19.2 C20.2 C21.2 C22.2 C23.2 C24.2 C25.2 C26.2 C27.2 C28.2 C29.2 C30.2 C31.2 C32.2 C33.2 C34.2 C35.2 C36.2 C37.1 C38.2 C39.2 C40.2 C41.2 C42.2 C43.1 C44.2 C53.2 C54.2 C55.2 C56.2 D3.1 D3.2 IC1.2 IC2.4 IC3.3 IC4.4 IC4.9 J101.1 J102.3 J102.5 J102.7 J102.9 LED101.2 LED102.2 R24.2 R25.2 R26.2 R27.2 R32.1 R37.1 R44.1 R46.1 R49.1 R52.1 R53.1 R54.1 R86.2 R88.1 R90.1 TP4.1 U2.1@836.63,2819.57 XDS1.10 XDS1.17 XDS1.48 XDS1.55 XDS1.58 XDS1.64 XDS1.66 XDS1.80 XDS1.114 XDS2.13 XDS2.14 XDS2.17 Y3.2 Y3.4 | length 9950.1
  Top Layer w8: C53.2@187,3899.23 171,3883.23 v1(171,3795) 171,3703.38 C13.2@207.38,3667 ; R88.1@207.38,3000 174.5,3000 ; C18.2@207.38,3477.61 207.38,3321 C19.2@206.38,3320 206.38,3292 ; XDS1.114@344.85,3304.38 291.59,3304.38 279.21,3292 206.38,3292 ; v1(446.69,3858.31) IC3.3@446.69,3892.19 ; C30.2@452.72,3759.62 496.82,3759.62 Y3.4@511.69,3774.5 511.69,3787.9 C29.2@550.75,3826.97 587.18,3863.39 642.22,3863.39 ; XDS1.10@545.64,3024.85 545.64,2990.66 551.91,2984.39 645.68,2984.39 650.78,2989.49 ; Y3.2@598.31,3711.5 639.98,3711.5 642.22,3713.74 ; XDS1.17@655.87,3024.85 655.87,2994.58 650.78,2989.49 ; XDS1.80@655.87,3631.15 655.87,3690.2 642.22,3703.85 642.22,3713.74 ; C54.2@728,4060 728,3928.5 R86.2@724.5,3925 ; XDS1.66@876.35,3631.15 876.35,3666.02 913,3702.68 913,3741.62 C14.2@882,3772.62 828,3772.62 828,3821.5 v1(812,3837.5) R86.2@724.5,3925 ; XDS1.48@951.15,3320.13 905.45,3320.13 868.12,3282.79 844.96,3282.79 838,3289.75 838,3431 ; XDS1.55@951.15,3430.36 838.64,3430.36 838,3431 ; XDS1.58@951.15,3477.61 838.61,3477.61 838,3477 ; XDS1.64@951.15,3572.22 858.22,3572.22 838,3552 v1(838,3525) 838,3477 ; C28.2@1109.62,3678 R26.2@1109.62,3522 R32.1@1109.62,3418 ; C15.2@1110.13,3314 1110.13,3365.5 C16.2@1109.62,3366 R32.1@1109.62,3418 ; v1(1423.8,2731.35) 1500.62,2731.35 IC2.4@1518.56,2749.29 ; R46.1@1428.38,3163 C35.2@1428.38,3217 1382,3263.38 1382,3336.5 1424.5,3379 R44.1@1428.38,3379 C34.2@1428.38,3432 ; v3(1557,3603) 1551.41,3603 1505.88,3557.47 1505.88,3557.25 1495.47,3546.83 1495.24,3546.83 1428.38,3479.97 C34.2@1428.38,3432 ; C31.2@1717,3659.24 1751,3625.24 1751,3577.24 R37.1@1717,3543.24 v1(1803,3457.24) 1830.89,3429.35 C42.2@1883.38,3429.35 1884.38,3428.35 C44.2@1884.38,3376 ; v1(1810.75,3323) R49.1@1884.76,3323 ; D3.2@1996.6,3467.41 v1(1996.6,3493) D3.1@1996.6,3518.59 ; 174.5,3000 v1(90.5,2916) 77.59,2903.09 77.59,2815.41 76.47,2814.29 LED102.2@76.47,2734 125.47,2685 J101.1@455,2685 467.5,2697.5 C17.2@467.5,2865.38 C21.2@524,2865.38 524,2853 552,2825 596.99,2825 C26.2@638,2866.01 C27.2@695,2866.01 718.01,2843 779,2843 800.75,2821.25 834.95,2821.25 U2.1@836.63,2819.57 838.32,2821.25 859.29,2821.25 897,2858.96 C22.2@897,2864.76 802.76,2959 v1(770,2959) 681.27,2959 650.78,2989.49 ; 174.5,3000 174.5,3101.5 180,3107 R54.1@207.38,3107 206.38,3108 C24.2@206.38,3213 C23.2@206.38,3266 206.38,3292 ; 642.22,3713.74 642.22,3863.34 669.23,3863.34 724.5,3918.62 R86.2@724.5,3925 ; 838,3431 838,3477 ; R32.1@1109.62,3418 v1(1210,3418) v1(1330,3418) 1414.38,3418 C34.2@1428.38,3432
  Top Layer w16: R86.2@724.5,3925 930,3925 ; C55.2@930,3995.95 930,3925 ; C56.2@1112.1,3897.58 1069,3940.68 1069,3993.39 IC4.9@1055.61,4006.78 ; v3(1557,3603) 1595.39,3641.39 XDS2.13@1595.39,3677.8 1586,3677.8 ; XDS2.14@1569.8,3677.8 1586,3677.8 ; R52.1@1875.5,3655.41 1725.34,3805.58 C32.2@1642.2,3805.58 ; R53.1@1931.24,3268 1931.24,3273 1981.38,3273 C39.2@1997,3288.62 2012.87,3304.5 C40.2@2070,3304.5 2101.5,3273 2171,3273 2180,3264 2180,3202.39 2159.38,3181.76 C41.2@2159.38,3179 2124,3179 v2(2100,3155) ; C38.2@2165.38,3784 2165.38,3830.99 C37.1@2146.5,3849.87 2146.5,3872.68 C36.2@2093.18,3926 2037.1,3869.92 1706.54,3869.92 C32.2@1642.2,3805.58 ; IC1.2@2183,3335 v2(2183,3374) 2183,3383.5 C43.1@2208.5,3409 ; 930,3925 1022.77,3925 1040.25,3942.49 1040.25,3991.43 IC4.9@1055.61,4006.78 ; IC4.9@1055.61,4006.78 1093.99,4045.17 IC4.4@1110.73,4045.17 1360.63,4045.17 1531.8,3874 1573.77,3874 C32.2@1642.2,3805.58 ; 1586,3677.8 1589,3680.8 C33.2@1589,3728 1589,3752.38 C32.2@1642.2,3805.58
  Top Layer w20: J102.3@1750,2719.88 J102.5@1800,2719.88 J102.7@1850,2719.88 J102.9@1900,2719.88 v1(1983.12,2719.88)
  other v1: 1102.68,2795.97 2072.1,2838.95 1912.66,3012.25 49.5,3035 1320,3205.04 780.01,3225.64 660,3374.32 749.88,3524.85 1280,3744.87 301.95,3754.84 979.85,3824.59 1724.24,3845.17 2255.75,3983.3
  other v3: 1557,3559.69 1513.69,3603 1600.31,3603 1557,3646.31 1055.61,3982.17 1035.92,4006.78 1075.29,4006.78 1055.61,4031.39
XDS_ID: IC3.2 USB2.4 XDS1.95 | length 630.1
  Top Layer w8: v1(412,3717.02) 412,3671.85 419.65,3664.2 XDS1.95@419.65,3631.15 ; IC3.2@427,3892.19 427,3880.9 408.04,3861.94 408.04,3838.4 417.44,3829 470.93,3829 481,3839.07 v1(481,3920) 481,3992.96 USB2.4@475.68,3998.28
  Bottom Layer w8: v1(412,3717.02) 412,3860.22 471.78,3920 v1(481,3920)
XDS_RESET_OUT: IC2.2 J101.11 J102.10 R85.1 XDS1.40 | length 2094.2
  Top Layer w8: v1(900,2794.5) 930,2824.5 930,2945.5 910,2965.5 910,3184.5 919.65,3194.14 XDS1.40@951.15,3194.14 1050.52,3194.14 R85.1@1063.38,3207 ; IC2.2@1491.99,2774.88 1442.09,2774.88 1418.72,2798.25 v1(1418.72,2926.46) 1476.26,2984 1868,2984 1900,2952 J102.10@1900,2880.12
  Bottom Layer w8: J101.11@955,2685 900,2740 v1(900,2794.5) 1048.5,2943 1402.18,2943 v1(1418.72,2926.46)
XDS_RXD: J101.9 XDS1.33 | length 491.4
  Top Layer w8: J101.9@855,2685 915,2745 950.09,2745 990,2784.91 990,3044.99 951.21,3083.78 XDS1.33@951.15,3083.78
XDS_TCK_SWDCLK: IC2.6 J101.15 J102.4 XDS1.35 | length 1676.4
  Top Layer w8: XDS1.35@951.15,3115.4 1056.6,3115.4 1155,3017 J101.15@1155,2685 ; v1(1490,2684) 1500.93,2694.93 1549.85,2694.93 1570,2715.08 1570,2767 1562.12,2774.88 IC2.6@1545.14,2774.88 ; v1(1710,2796) 1736,2796 1750,2810 J102.4@1750,2880.12
  Bottom Layer w8: J101.15@1155,2685 1257,2787 1317.62,2787 1380.23,2849.61 1490,2849.61 ; v1(1490,2684) 1490,2849.61 ; v1(1710,2796) 1672,2796 1618.39,2849.61 1490,2849.61
XDS_TDI: IC2.3 J102.8 XDS1.38 | length 1505.7
  Top Layer w8: XDS1.38@951.15,3162.65 1128.16,3162.65 1169.2,3203.68 1262.15,3203.68 1355.89,3109.95 v1(1355.89,2898.31) 1355.89,2834.08 1355,2833.2 1432.85,2755.35 1491.83,2755.35 IC2.3@1491.99,2755.19 ; v1(1520.04,2930) 1554.04,2964 1839,2964 1850,2953 J102.8@1850,2880.12
  Bottom Layer w8: v1(1355.89,2898.31) 1488.35,2898.31 v1(1520.04,2930)
XDS_TDO_SWO: IC2.5 J102.6 XDS1.37 | length 1713
  Top Layer w8: XDS1.37@951.15,3146.9 1038.1,3146.9 ; 1038.1,3146.77 1152.8,3146.77 1193.68,3187.65 1243.88,3187.65 1255,3176.53 v1(1255,2827) 1255,2800.97 1303.97,2752 1365.81,2752 1416.7,2701.11 1416.59,2701 1469,2701 1483.31,2715.31 1525.31,2715.31 1545.14,2735.14 IC2.5@1545.14,2755.19 ; v1(1601,2924) 1623.85,2946.85 1773.94,2946.85 1800,2920.79 J102.6@1800,2880.12
  Bottom Layer w8: v1(1255,2827) 1319.83,2827 1359.17,2866.34 1543.34,2866.34 v1(1601,2924)
XDS_TMS_SWDIO: IC2.7 J101.13 J102.2 XDS1.36 | length 1587.2
  Top Layer w8: XDS1.36@951.15,3131.15 1072.85,3131.15 ; J101.13@1055,2685 1097.39,2642.61 1488.61,2642.61 1521,2675 1563,2675 1591,2703 1591,2794.56 ; 1072.85,3130.9 1073.1,3130.9 1200,3004 v1(1200,2795) ; IC2.7@1545.14,2794.56 1591,2794.56 ; J102.2@1700,2880.12 1700,2860 1634.56,2794.56 1591,2794.56
  Bottom Layer w8: J101.13@1055,2685 1119,2749 1177.96,2749 1200,2771.04 v1(1200,2795)
XDS_TXD: J101.7 XDS1.34 | length 719.8
  Top Layer w8: J101.7@755,2685 833,2763 918,2763 v1(950,2795) ; XDS1.34@951.15,3099.65 1014.6,3099.65 ; 1014.6,3099.53 1014.73,3099.53 1060,3054.25 1060,2825 v1(1030,2795)
  Bottom Layer w8: v1(950,2795) v1(1030,2795)
XDS_VBUS: C36.1 C37.2 C38.1 C53.1 C55.1 IC3.6 IC4.5 IC4.8 J101.3 R28.1 R48.2 R87.1 R89.2 T1.2 | length 4797
  Top Layer w6: v1(321,3869) 349,3869 389.06,3909.06 400.57,3909.06 IC3.6@407.32,3915.81
  Top Layer w8: C53.1@187,3962.22 220,3929.22 220,3732.62 R28.1@207.38,3720
  Top Layer w16: C53.1@187,3962.22 R89.2@260,3962.22 303.78,3962.22 v2(321,3945) ; v2(205,2895) 205,2944.62 R87.1@207.38,2947 ; C55.1@928.03,4045.17 C55.1@930,4043.2 ; IC4.8@1000.49,3968.39 996.88,3972.01 983.25,3972.01 972.8,3982.45 972.8,4031.31 973,4031.5 973,4043.2 ; IC4.5@1000.49,4045.17 998.52,4043.2 973,4043.2 ; T1.2@2154,3597.82 2219,3662.82 2219,3884.49 2123.49,3980 2030,3980 1990.82,3940.82 C36.1@1990.82,3926 1552,3926 1363,4115 961.61,4115 930,4083.39 C55.1@930,4043.2 ; C55.1@930,4043.2 973,4043.2
  Top Layer w20: v2(871,4045.17) C55.1@928.03,4045.17
  Bottom Layer w20: J101.3@555,2685 345,2895 v2(205,2895) 178.5,2895 128,2945.5 128,3495 256.62,3623.62 256.62,3804.62 v1(321,3869) v2(321,3945) 404,4028 853.83,4028 v2(871,4045.17)
XDS_VCC: C14.1 C15.1 C16.1 C17.1 C18.1 C19.1 C21.1 C22.1 C32.1 C33.1 C41.1 C56.1 IC1.5 IC2.8 IC4.1 J102.1 R31.2 R34.2 R35.2 R41.2 R42.2 R43.2 R45.2 R51.2 R85.2 R91.1 R92.1 TP10.1 XDS1.7 XDS1.8 XDS1.16 XDS1.26 XDS1.28 XDS1.39 XDS1.47 XDS1.51 XDS1.52 XDS1.69 XDS1.79 XDS1.90 XDS1.101 XDS1.113 XDS1.122 XDS2.15 XDS2.16 | length 4652.9
  Top Layer w8: v1(110.33,3666) 129.2,3647.13 R91.1@142,3647.13 ; R92.1@142,3533.76 169.76,3506 226.23,3506 C18.1@254.62,3477.61 ; R51.2@208,3054 235,3027 v1(349,3027) ; C19.1@253.62,3320 C19.1@253.75,3320.13 ; XDS1.122@344.85,3178.39 393.39,3178.39 v1(420,3205) ; XDS1.113@344.85,3320.13 C19.1@253.75,3320.13 ; C17.1@467.5,2912.62 C21.1@524,2912.62 ; XDS1.90@498.39,3631.15 498.39,3571.39 436.1,3509.1 XDS1.101@344.85,3509.1 286.12,3509.1 C18.1@254.62,3477.61 ; XDS1.8@514.14,3024.85 XDS1.7@498.39,3024.85 v1(498.39,2969.61) 524,2944 C21.1@524,2912.62 ; R34.2@580.4,2866.01 533.79,2912.62 C21.1@524,2912.62 ; XDS1.16@640.13,3024.85 640.13,3055.13 650,3065 789,3065 797.61,3056.39 XDS1.26@797.61,3024.85 797.61,2984.39 802.1,2979.9 v1(829.1,2979.9) ; XDS1.79@671.62,3631.15 671.62,3715.06 663,3723.68 663,3779.06 692.94,3809 v1(748,3809) 774,3783 R31.2@774,3772.62 ; XDS1.69@829.1,3631.15 829.1,3672.48 v1(843,3686.38) C14.1@882,3725.38 ; C22.1@897,2912 v1(829.1,2979.9) ; XDS1.39@951.15,3178.39 1082.02,3178.39 R85.2@1110.62,3207 1110.62,3266.26 C15.1@1062.88,3314 ; XDS1.52@951.15,3383.12 XDS1.51@951.15,3367.37 1061.01,3367.37 C16.1@1062.38,3366 1062.88,3365.5 C15.1@1062.88,3314 ; 1172.61,3968.39 1174,3967 ; R45.2@1428.38,3271 1428.38,3278.76 R43.2@1475.62,3326 1500.27,3326 R42.2@1551,3376.73 1551.65,3377.38 R41.2@1613,3377.38 1613,3338 v1(1600,3325) ; IC2.8@1518.56,2800.47 1542.24,2824.15 v1(1565.85,2824.15) ; v1(1607,2664) 1621,2650 1684.72,2650 1700,2665.28 J102.1@1700,2719.88 ; C19.1@253.75,3320.13 254.62,3321 v1(254.62,3385) C18.1@254.62,3477.61 ; v1(829.1,2979.9) XDS1.28@829.1,3024.85 829.1,3142.31 901,3214.21 901,3287 918.38,3304.38 XDS1.47@951.15,3304.38 1053.26,3304.38 C15.1@1062.88,3314
  Top Layer w16: R35.2@1109,3730 1208,3829 v1(1208,3875) 1470.41,3875 C32.1@1539.84,3805.58 1539.84,3682.17 XDS2.15@1544.2,3677.8 XDS2.16@1518.61,3677.8 ; IC4.1@1110.73,3968.39 1172.61,3968.39 ; v2(2200,3125) 2206.62,3131.62 C41.1@2206.62,3179 2220.4,3192.78 IC1.5@2220.4,3226.73
  Bottom Layer w8: v1(1565.85,2824.15) 1598.85,2824.15 1607,2816 v1(1607,2664)
  other v1: 1208,3915 1208,3955
XDS_VCCOUT: C42.1 C43.2 C44.1 IC1.3 L1.2 R36.2 R38.2 R39.2 R40.2 | length 830.6
  Top Layer w8: R36.2@1717,3376.38 1745.38,3348 1903.62,3348 C44.1@1931.62,3376
  Top Layer w25: R39.2@1930,3594.2 R40.2@1930,3539 1930,3408.85 ; C44.1@1931.62,3376 1930,3377.62 1930,3408.85 ; L1.2@2145.06,3493 2145.06,3409.44 C43.2@2145.5,3409 ; IC1.3@2145.6,3335 2145.5,3335.09 C43.2@2145.5,3409 ; 1930,3408.85 1930.15,3409 C43.2@2145.5,3409
XDS_VCCTARGET: C39.1 C40.1 IC1.4 J101.5 R50.2 | length 1787.4
  Top Layer w25: v2(1830,3015) 1931.62,3116.62 R50.2@1931.62,3214 1953.44,3235.81 1997,3235.81 C39.1@1997,3241.38 2130.95,3241.38 IC1.4@2145.6,3226.73
  VCC Layer w25: J101.5@655,2685 833,2863 1678,2863 v2(1830,3015)
pads on no net: FID1.1 FID2.1 FID3.1 IC4.2 IC4.3 IC4.6 IC4.7 J103.6 J103.8 MH1.1 MH2.1 MH3.1 MH4.1 RT1.1S RT1.2S S1. S2. S3. SH-J1.0 SH-J2.0 SH-J3.0 SH-J4.0 SH-J5.0 SH-J6.0 SH-J7.0 SH-J8.0 SH-J9.0 SH-J10.0 SH-J11.0 SH-J12.0 SH-J13.0 SH-J14.0 SH-J15.0 SH-J16.0 SH-J17.0 SH-J18.0 SH-J19.0 SH-J20.0 SH-J21.0 SH-J22.0 SH-J23.0 SH-J24.0 SH-J25.0 U1.1 U1.3 U2.2@836.63,2845.16 U2.4@748.05,2870.75 U2.5@748.05,2819.57 XDS1.2 XDS1.12 XDS1.13 XDS1.14 XDS1.15 XDS1.18 XDS1.19 XDS1.20 XDS1.21 XDS1.22 XDS1.23 XDS1.24 XDS1.25 XDS1.29 XDS1.30 XDS1.31 XDS1.32 XDS1.41 XDS1.43 XDS1.44 XDS1.45 XDS1.46 XDS1.53 XDS1.54 XDS1.56 XDS1.57 XDS1.65 XDS1.67 XDS1.71 XDS1.72 XDS1.73 XDS1.74 XDS1.75 XDS1.76 XDS1.81 XDS1.82 XDS1.83 XDS1.84 XDS1.85 XDS1.86 XDS1.91 XDS1.92 XDS1.102 XDS1.103 XDS1.104 XDS1.105 XDS1.106 XDS1.107 XDS1.108 XDS1.109 XDS1.110 XDS1.111 XDS1.112 XDS1.116 XDS1.117 XDS1.118 XDS1.119 XDS1.121 XDS1.123 XDS1.124 XDS1.125 XDS1.126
